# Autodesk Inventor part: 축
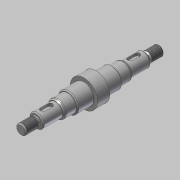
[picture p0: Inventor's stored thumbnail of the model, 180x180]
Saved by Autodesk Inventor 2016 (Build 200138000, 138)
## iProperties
Created: 2019-09
Part Number: 축
Material: 강철, 연강
Document SubType Name: Modeling
Designer: mduedu
Density: 7.86 g/cm^3
Mass: 210.278 g
Surface Area: 69.4769 cm^2
Volume: 26.7529 cm^3
Appearance: 강철
Author: mduedu
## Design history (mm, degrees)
sketch "스케치1"
  geometry: L1 (0, 0)-(15, 0); L2 (15, 0)-(15, 5); L3 (15, 5)-(0, 5); L4 (0, 5)-(0, 0); L5 (15, 0)-(34, 0); L6 (34, 0)-(34, 7); L7 (34, 7)-(15, 7); L8 (15, 7)-(15, 0); L9 (34, 0)-(46, 0); L10 (46, 0)-(46, 8.5); L11 (46, 8.5)-(34, 8.5); L12 (34, 8.5)-(34, 0); L13 (46, 0)-(62, 0); L14 (62, 10)-(46, 10); L15 (46, 10)-(46, 0); L16 (62, 10)-(62, 0); L17 (62, 0)-(68, 0); L18 (68, 0)-(68, 13.5); L19 (68, 13.5)-(62, 13.5); L20 (62, 13.5)-(62, 0)
  constraints: 40 end point, 10 parallel, 5 horizontal, 4 perpendicular, 1 vertical
  dimensions: "d2" = 15 distance of L2.end L3.end; "d3" = 19 distance of L6.end L7.end; "d8" = 16 distance of L14.start L14.end; "d9" = 10 diameter of L3 L1; "d10" = 14 diameter of L7 L5; "d11" = 17 diameter of L11 L9; "d12" = 20 diameter of L14 L13; "d73" = 12 distance of L10.end L11.end (derived); "d74" = 27 diameter of L19 L17; "d75" = 6 distance of L18.end L19.end; "d76" = 68 distance between parallel lines of L4 L18
revolve "회전1" sketch "스케치1" stored, may be unused: angle "d17" = 90 deg
revolve "회전2" stored, may be unused: angle "d22" = 90 deg
fillet "모깎기1" dims "d23" = 0.6
feature "스레드1" dims "d24" = 10, "d25" = 0
chamfer "모따기1" distance "d26" = 1; stored, may be unused: second distance "d27" = 2, angle "d28" = 45 deg
chamfer "모따기2" distance "d29" = 1; stored, may be unused: second distance "d30" = 2, angle "d31" = 45 deg
chamfer "모따기3" distance "d32" = 1.819; stored, may be unused: second distance "d33" = 2, angle "d34" = 30 deg
fillet "모깎기2" dims "d35" = 2
chamfer "모따기4" distance "d36" = 1; stored, may be unused: second distance "d37" = 2, angle "d38" = 30 deg
fillet "모깎기3" dims "d39" = 0.3
node "작업 평면1"
sketch "스케치3" dims "d51" = 12
  geometry: L1 (3, -2.5)-(-4, -2.5); L2 (-4, -2.5)-(-4, 2.5); L3 (-4, 2.5)-(3, 2.5); L4 (3, 2.5)-(3, -2.5); L5 (-9.5, 7.45)-(-9.5, -7.45) reference; 3 further points
  constraints: 8 end point, 2 midpoint, 2 parallel, 2 vertical alignment, 1 horizontal, 1 horizontal alignment, 1 perpendicular, 4 other
  dimensions: "d50" = 3 dimension on L5; "d52" = 5 distance between parallel lines of L3 L1
extrude "돌출1" cut sketch "스케치3" distance "d53" = 3; taper "d54" = 0 deg
node "솔리드1"
mirror "대칭1"
sketch "스케치2"
  geometry: L1 (0, -5)-(0, 5) reference; L2 (0, 5)-(15, 5) reference; L3 (15, 5)-(15, 7) reference; L4 (15, 7)-(34, 7) reference; L5 (34, 7)-(34, 8.5) reference; L6 (34, 8.5)-(46, 8.5) reference; L7 (46, 8.5)-(46, 10) reference; L8 (46, 10)-(62, 10) reference; L9 (62, -10)-(46, -10) reference; L10 (46, -10)-(46, -8.5) reference; L11 (46, -8.5)-(34, -8.5) reference; L12 (34, -8.5)-(34, -7) reference; L13 (34, -7)-(15, -7) reference; L14 (15, -7)-(15, -5) reference; L15 (15, -5)-(0, -5) reference; L16 (0, 0)-(74, 0); L17 (15, 5)-(12.014, 5); L18 (13.4, 4.2)-(15, 4.2); L19 (15, 4.2)-(15, 5); L20 (12.014, 5)-(13.4, 4.2); L21 (62, 10)-(62, 13.5) reference; L22 (62, 13.5)-(68, 13.5) reference; L23 (68, 13.5)-(68, -13.5) reference; L24 (68, -13.5)-(62, -13.5) reference; L25 (62, -13.5)-(62, -10) reference
  constraints: 10 end point, 1 horizontal, 1 parallel, 1 vertical
  dimensions: "d18" = 30 deg angle of L2 L20; "d19" = 8.4 diameter of L18 L16; "d21" = 2.986 distance from line of L17.end L19
node "절단 모서리 투영1"
